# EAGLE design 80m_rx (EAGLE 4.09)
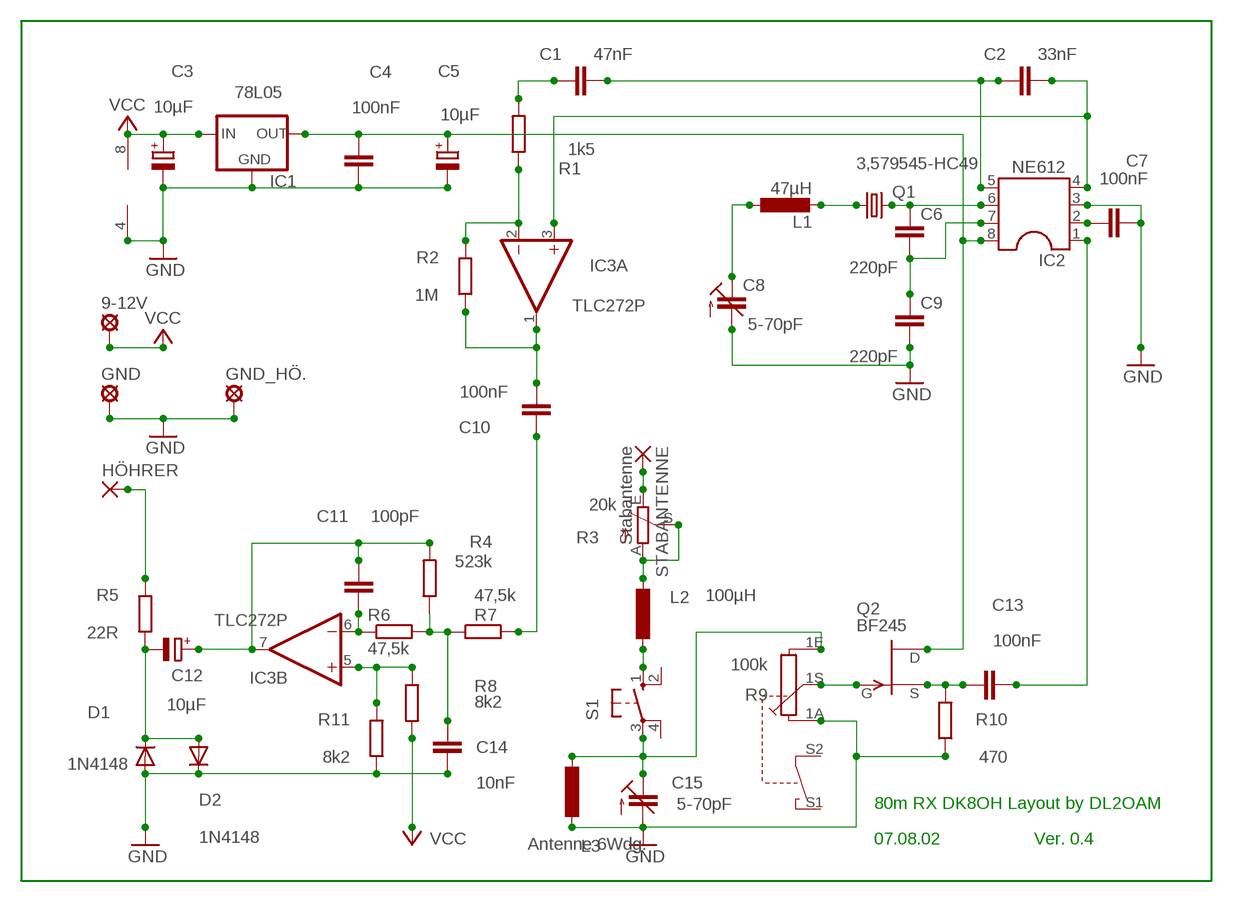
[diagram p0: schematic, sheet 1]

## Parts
9-12V  SE14  [SE14]
C1  47nF  C2.5/2  [C2.5-2]
C2  33nF  C-EU025-024X044  [C025-024X044]
C3  10µF  CPOL-EUE2.5-7  [E2,5-7]
C4  100nF  C-EU025_050-035X075  [C025_050-035X075]
C5  10µF  CPOL-EUE2.5-7  [E2,5-7]
C6  220pF  C2.5/2  [C2.5-2]
C7  100nF  C-EU025_050-025X075  [C025_050-025X075]
C8  5-70pF  C-TRIMM808-7.5  [CTRIM808-BC7.5]
C9  220pF  C2.5/2  [C2.5-2]
C10  100nF  C-EU025_050-025X075  [C025_050-025X075]
C11  100pF  C2.5/2  [C2.5-2]
C12  10µF  CPOL-EUE2.5-7  [E2,5-7]
C13  100nF  C-EU025_050-035X075  [C025_050-035X075]
C14  10nF  C-EU025-024X044  [C025-024X044]
C15  5-70pF  C-TRIMM808-7.5  [CTRIM808-BC7.5]
D1  1N4148  [DO35-10]
D2  1N4148  [DO35-10]
GND  SE14  [SE14]
GND_HÖ.  SE14  [SE14]
HÖHRER  3,81/1,1  [3,81/1,1]
IC1  78L05  78LXX  [78LXX]
IC2  NE612  DIL8  [DIL08]
IC3  TLC272P  [DIL08]
L1  47µH  L-EU0207/10  [0207/10]
L2  100µH  L-EU0207/12  [0207/12]
L3  Antenne 6Wdg.  L-EU0207/12  [0207/12]
Q1  3,579545-HC49  CRYTALHC49S  [HC49/S]
Q2  BF245  [TO92]
R1  1k5  R-EU_0207/10  [0207/10]
R2  1M  R-EU_0207/10  [0207/10]
R3  20k  TRIM_EU-S75H  [S75H]
R4  523k  R-EU_0207/10  [0207/10]
R5  22R  R-EU_0309/10  [0309/10]
R6  47,5k  R-EU_0309/10  [0309/10]
R7  47,5k  R-EU_0207/10  [0207/10]
R8  8k2  R-EU_0309/10  [0309/10]
R9  100k  PC16SV  [PC16SV]
R10  470  R-EU_0207/10  [0207/10]
R11  8k2  R-EU_0309/10  [0309/10]
S1  40-XX  [B3F-40XX]
STABANTENNE  Stabantenne  3,81/1,1  [3,81/1,1]

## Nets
8V: C4.1 C5.+ IC1.OUT IC2.8 Q2.1(D)
GND: C3.- C4.2 C5.- C7.2 C8.2(A) C9.2 C14.2 C15.2(A) D1.A D2.C GND.MP GND_HÖ..MP IC1.GND IC2.3 IC3.4(P:V-) L3.1 R9.1A R10.1 R11.1
N$2: R3.E STABANTENNE.1(P)
N$3: L2.2 R3.A R3.S
N$4: L2.1 S1.1(S)
N$5: C15.1(E) L3.2 R9.1E S1.3(P)
N$6: Q2.3(G) R9.1S
N$7: C13.1 Q2.2(S) R10.2
N$8: C7.1 IC2.2
N$11: C1.2 C2.1 IC2.5
N$12: C1.1 R1.2
N$15: IC3.2(A:-IN) R1.1 R2.2
N$16: C14.1 R4.1 R6.2 R7.1
N$17: C8.1(E) L1.1
N$18: C10.2 IC3.1(A:OUT) R2.1
N$19: C10.1 R7.2
N$20: C11.2 C12.+ IC3.7(B:OUT) R4.2
N$21: C12.- D1.C D2.A R5.1
N$22: HÖHRER.1(P) R5.2
N$24: C13.2 IC2.1
N$26: IC3.5(B:+IN) R8.1 R11.2
N$29: C11.1 IC3.6(B:-IN) R6.1
OSC: C6.1 IC2.6 Q1.2
OSC2: C6.2 C9.1 IC2.7
OSC3: L1.2 Q1.1
OUTPUTA: C2.2 IC2.4 IC3.3(A:+IN)
VCC: 9-12V.MP C3.+ IC1.IN IC3.8(P:V+) R8.2
Unconnected: R9.S1 R9.S2 S1.2(S1) S1.4(P1)

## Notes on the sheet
- 80m RX DK8OH Layout by DL2OAM
- 07.08.02 | Ver. 0.4

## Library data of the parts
9-12V GND GND_HÖ. = solpad:SE14: SOLDER PAD
C1 C6 C9 C11 = capacitor-wima:C: CAPACITOR
C2 C4 C7 C10 C13 C14 = rcl:C-EU: CAPACITOR, European symbol
C3 C5 C12 = rcl:CPOL-EU: POLARIZED CAPACITOR, European symbol
C8 C15 = rcl:C-TRIMM: Trimm capacitor
D1 D2 = diode:1N4148: DIODE
HÖHRER STABANTENNE = wirepad:3,81/1,1: THROUGH-HOLE PAD
IC1 = v-reg:78LXX: VOLTAGE REGULATOR
IC2 = dil:DIL8: SOCKET Dual In Line
IC3 = linear:TLC272: OP AMP
L1-L3 = rcl:L-EU: INDUCTOR, European symbol
Q1 = crystal:CRYTAL: CRYSTAL
Q2 = transistor-fet:BF245: N-Channel Junction FET
R1 R2 R4-R8 R10 R11 = rcl:R-EU_: RESISTOR, European symbol
R3 = pot:TRIM_EU-: POTENTIOMETER
R9 = piher:PC16SV: POTENTIOMETER vertical single carbon potentiometer with switch, 16 mm
S1 = switch-omron:40-XX: OMRON SWITCH

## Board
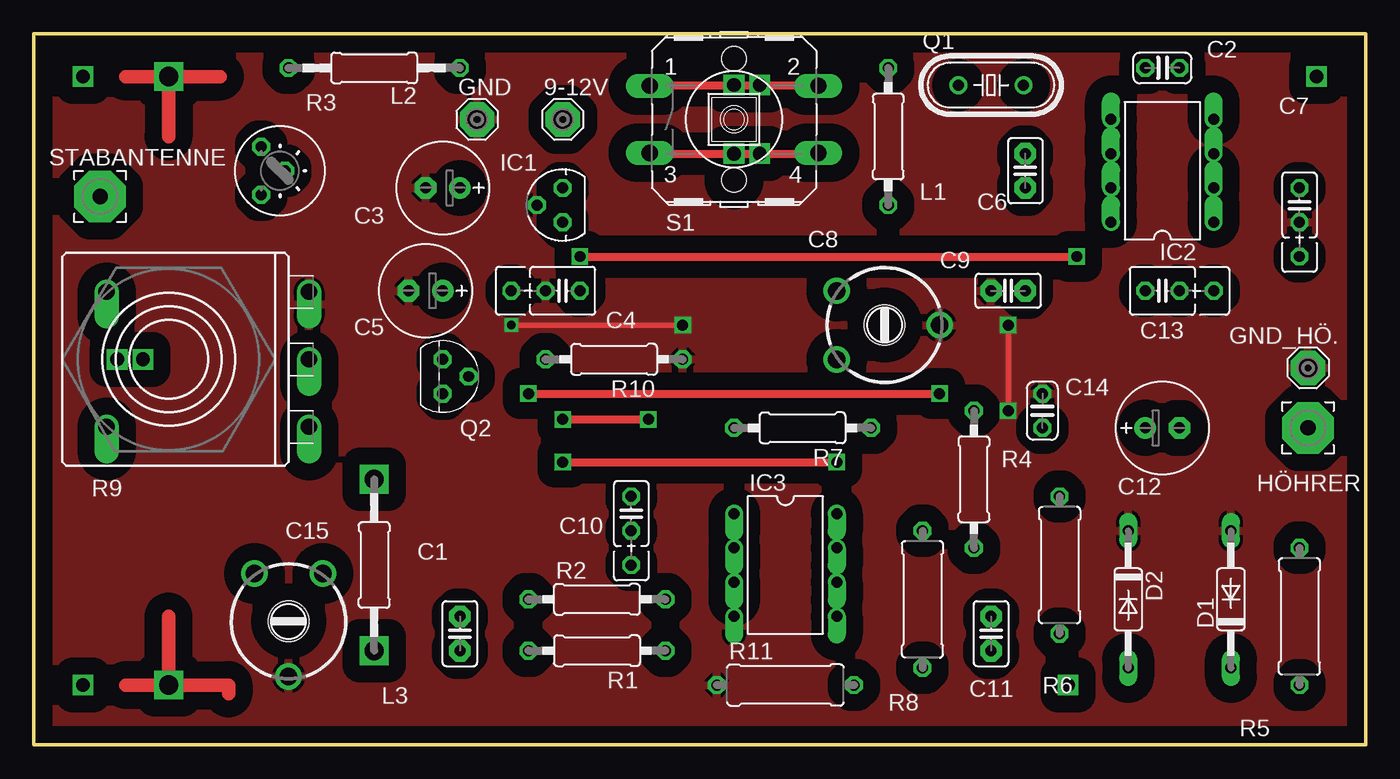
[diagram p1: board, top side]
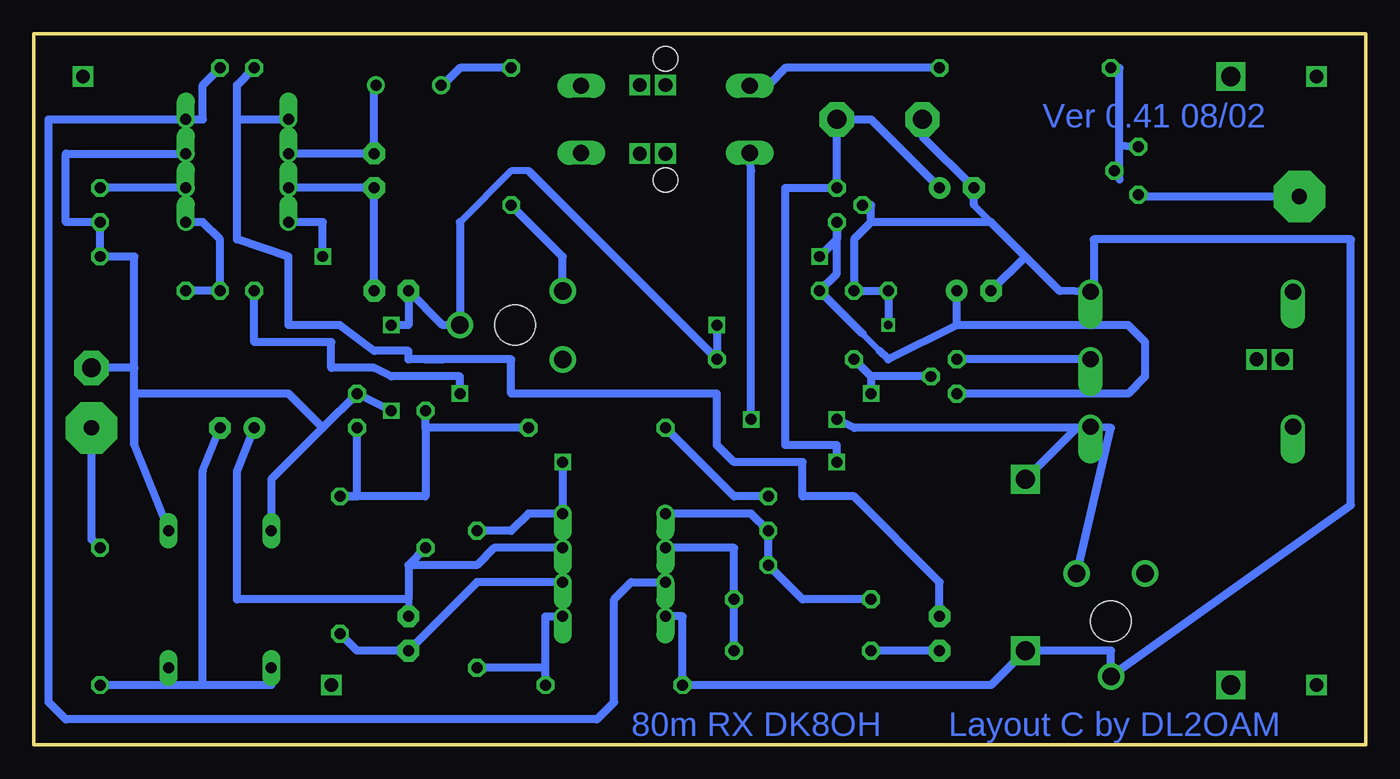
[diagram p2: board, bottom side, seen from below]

Size 98.73 x 52.7 mm. Coordinates in mm from the lower left corner, seen from the top.
Outline: 0,0 98.73,0 98.73,52.7 0,52.7 0,0
Copper layers used: Top, Bottom

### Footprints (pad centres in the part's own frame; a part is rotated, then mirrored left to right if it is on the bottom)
SE14 = drill 1.397 pad 2.54 octagon: MP 0,0
C2.5-2 = drill 0.813 pad 1.6 octagon: 1 -1.27,0; 2 1.27,0
C025-024X044 = drill 0.813 octagon: 1 -1.27,0; 2 1.27,0
E2,5-7 = drill 0.813 pad 1.6 round: + -1.27,0 | drill 0.813 pad 1.6 octagon: - 1.27,0
C025_050-035X075 = drill 0.813 octagon: 1 -1.27,0; 2 1.27,0; 3 3.81,0
C025_050-025X075 = drill 0.813 octagon: 1 -1.27,0; 2 1.27,0; 3 3.81,0
CTRIM808-BC7.5 = drill 1.3 round: 1 -2.54,-2.54; 2 0,5.08; 3 2.54,-2.54 | hole 3: 0,1
DO35-10 = drill 0.813 long: A 5.08,0; C -5.08,0
3,81/1,1 = drill 1.118 pad 3.81 octagon: 1 0,0
78LXX = drill 0.813 octagon: GND 0,1.905; IN 1.27,0; OUT -1.27,0
DIL08 = drill 0.813 offset: 1 -3.81,-3.81; 2 -1.27,-3.81; 3 1.27,-3.81; 4 3.81,-3.81; 5 3.81,3.81; 6 1.27,3.81; 7 -1.27,3.81; 8 -3.81,3.81
0207/10 = drill 0.813 octagon: 1 -5.08,0; 2 5.08,0
0207/12 = drill 0.813 octagon: 1 -6.35,0; 2 6.35,0
HC49/S = drill 0.813 round: 1 -2.413,0; 2 2.413,0
TO92 = drill 0.813 octagon: 1 1.27,0; 2 0,1.905; 3 -1.27,0
S75H = drill 0.813 octagon: A -1.778,-1.397; E 1.778,-1.397; S 0,0.381
0309/10 = drill 0.813 octagon: 1 -5.08,0; 2 5.08,0
PC16SV = drill 1.2 offset: 1A -5,10.4; 1E 5,10.4; 1S 0,10.4; S1 -5,-4.6; S2 5,-4.6
B3F-40XX = drill 1.194 long: 1 -6.248,2.489; 2 6.248,2.489; 3 -6.248,-2.489; 4 6.248,-2.489 | hole 1.803: 0,-4.496; 0,4.496

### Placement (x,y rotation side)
9-12V  39.2,46.35 0 top
C1  31.59,8.25 90 top
C2  83.66,50.16 0 top
C3  30.32,41.27 180 top
C4  39.2,33.65 180 top
C5  29.05,33.65 180 top
C6  73.5,42.54 270 top
C7  93.81,40 270 top
C8  62.06,31.11 270 top
C9  72.23,33.65 180 top
C10  44.28,17.14 270 top
C11  70.95,8.25 90 top
C12  83.66,23.49 0 top
C13  83.66,33.65 0 top
C14  74.77,24.76 90 top
C15  18.89,10.16 180 top
D1  88.73,10.79 90 top
D2  81.12,10.79 270 top
GND  32.85,46.35 0 top
GND_HÖ.  94.45,27.93 0 top
HÖHRER  94.45,23.49 0 top
IC1  39.2,40 90 top
IC2  83.66,42.54 90 top
IC3  55.71,13.33 270 top
L1  63.33,45.08 90 top
L2  25.23,50.16 180 top
L3  25.23,13.33 90 top
Q1  70.95,48.89 0 top
Q2  30.32,27.3 270 top
R1  41.74,6.98 180 top
R2  41.74,10.79 0 top
R3  18.25,42.54 270 top
R4  69.69,19.68 270 top
R5  93.81,9.52 90 top
R6  76.04,13.33 90 top
R7  56.98,23.49 180 top
R8  65.88,10.79 90 top
R9  10,28.57 270 top
R10  43.01,28.57 180 top
R11  55.71,4.44 0 top
S1  51.9,46.35 0 top
STABANTENNE  4.92,40.63 0 top

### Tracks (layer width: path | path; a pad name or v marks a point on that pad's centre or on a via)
8V  (via drill 0.81)
  Top 0.61: v40.47,36.19 v77.31,36.19
  Bottom 0.406: 36.03,29.2 37.3,30.47
  Bottom 0.61: v40.47,36.19 39.2,37.46 IC1.OUT 39.2,34.92 C4.1 37.3,30.47 | v77.31,36.19 77.31,38.73 IC2.8 | 30.32,31.11 35.39,28.57 36.03,29.2 | 30.32,31.11 C5.+ | 30.32,31.11 17.62,31.11 16.34,29.84 16.34,27.3 17.62,26.03 Q2.1
GND  (via drill 0.61, 0.81)
  Top 0.406: v72.23,31.11 v72.23,24.76 | v35.39,31.11 v48.09,31.11
  Bottom 0.508: 36.66,40 IC1.GND | 27.78,38.73 29.05,40 | 67.15,38.73 63.33,42.54 62.06,42.54
  Bottom 0.61: 77.31,23.49 C14.2 v72.23,24.76 | D2.C 81.12,19.68 77.31,23.49 | 91.28,22.22 D1.A | 91.28,22.22 91.28,27.93 GND_HÖ..MP | 91.28,26.03 91.28,22.22 | 77.31,23.49 79.84,26.03 91.28,26.03 | 36.66,38.73 37.93,37.46 C4.2 35.39,33.65 v35.39,31.11 | 36.66,38.73 36.66,40 | GND.MP 32.85,45.08 C3.- 29.05,40 | 25.23,36.19 22.7,33.65 R9.1A | 25.23,36.19 27.78,38.73 36.66,38.73 | IC3.4 50.63,9.52 R11.1 27.78,4.44 L3.1 18.89,6.98 C15.2 | C15.2 18.89,4.44 | IC2.3 96.36,43.81 96.36,38.73 C7.2 93.81,36.19 91.28,36.19 91.28,26.03 | 25.23,36.19 C5.- | 62.06,42.54 R10.1 v48.09,31.11 | 67.15,38.73 C8.2 68.42,31.11 C9.2 70.95,31.11 v72.23,31.11 | C15.2 1.1,17.77 1.1,37.46 20.16,37.46 20.16,33.65 20.79,33.65
  pour Top (isolate 1.27, rank 3): 0.47,52.06 0.47,-0.01 98.9,-0.01 98.9,52.7 0.47,52.7
N$2
  Bottom 0.61: R3.E 16.98,40.76 16.98,40.63 STABANTENNE.1
N$3
  Bottom 0.508: 18.89,42.54 R3.S 18.25,42.54
  Bottom 0.61: L2.2 18.25,50.16 18.25,44.45 | 18.25,41.91 18.25,42.54 18.25,44.45 | 18.25,44.45 R3.A
N$4
  Bottom 0.61: L2.1 43.01,50.16 44.28,48.89 S1.1
N$5  (via drill 0.81)
  Top 0.61: v39.2,24.12 v45.55,24.12
  Bottom 0.508: R9.1E 20.16,23.49
  Bottom 0.61: L3.2 21.43,23.49 R9.1E 18.89,23.49 C15.1 | v45.55,24.12 45.55,42.54 S1.3 | 20.16,23.49 37.93,23.49 v39.2,24.12
N$6
  Bottom 0.61: R9.1S Q2.3
N$7  (via drill 0.81)
  Top 0.61: v36.66,26.03 v67.15,26.03
  Bottom 0.61: 36.66,27.3 R10.2 | Q2.2 36.66,27.3 | C13.1 82.39,29.84 76.67,29.84 76.67,27.93 73.5,27.93 72.23,27.3 67.15,27.3 v67.15,26.03 | 36.66,27.3 v36.66,26.03
N$8
  Bottom 0.61: IC2.2 C7.1
N$9  (via drill 1.02)
  Top 0.61: 45.55,48.89 v51.9,48.89 v53.81,48.89 58.25,48.89
N$10  (via drill 1.02)
  other vias: 8.09,28.57
N$11
  Bottom 0.61: C1.2 31.59,12.06 37.93,18.41 41.74,18.41 41.74,20.95 46.82,20.95 48.09,22.22 48.09,26.03 63.33,26.03 63.33,28.57 69.69,28.57 | 69.69,28.57 68.42,28.57 | 69.69,28.57 70.95,28.57 70.95,29.2 73.5,29.2 76.04,31.11 79.84,31.11 79.84,36.19 83.66,37.46 83.66,46.35 | 83.66,46.35 83.66,48.89 C2.1 | 83.66,46.35 IC2.5
N$12
  Bottom 0.61: C1.1 R1.2
N$13  (via drill 1.02)
  other vias: 6.19,28.57
N$15
  Bottom 0.61: R1.1 R2.2 46.82,14.6 IC3.2
N$16
  Bottom 0.61: R7.1 69.69,23.49 | 69.69,23.49 R4.1 | C14.1 74.77,18.41 R6.2 69.69,18.41 69.69,23.49
N$17
  Bottom 0.61: L1.1 59.52,36.19 C8.1
N$18
  Bottom 0.61: R2.1 41.74,10.79 44.28,13.33 C10.2 45.55,17.14 IC3.1
N$19
  Bottom 0.61: C10.1 46.82,18.41 R7.2
N$20
  Bottom 0.508: 70.95,10.79 C11.2
  Bottom 0.61: 70.95,13.33 70.95,10.79 83.66,10.79 83.66,20.31 C12.+ | 70.95,13.33 R4.2 | 70.95,13.33 65.88,13.33 64.61,14.6 IC3.7
N$21
  Bottom 0.61: D2.A 81.12,4.44 86.2,4.44 | 86.2,4.44 R5.1 | 86.2,4.44 88.73,4.44 D1.C | 86.2,4.44 86.2,20.31 C12.-
N$22
  Bottom 0.61: HÖHRER.1 94.45,15.24 R5.2
N$23  (via drill 1.02)
  Top 0.61: 58.25,43.81 v53.81,43.81 v51.9,43.81 45.55,43.81
N$24
  Bottom 0.61: 87.47,33.65 C13.2 84.92,37.46 86.2,38.73 IC2.1
N$26
  Bottom 0.61: 60.79,5.71 60.79,9.52 IC3.5 | R11.2 60.79,5.71 | 60.79,5.71 R8.1
N$27  (via drill 1.02)
  other vias: 3.65,49.52
N$28  (via drill 1.02)
  other vias: 3.65,4.44
N$29
  Bottom 0.61: R6.1 74.77,6.98 C11.1 65.88,12.06 IC3.6
N$30  (via drill 1.02)
  other vias: 95.09,49.52
N$31  (via drill 1.02)
  other vias: 76.67,4.44
N$32  (via drill 1.42)
  other vias: 25.23,19.68
N$33  (via drill 1.42)
  other vias: 25.23,6.98
N$34  (via drill 1.42)
  Top 1.016: v10,4.44 14.44,4.44 14.44,3.8 | 9.36,4.44 v10,4.44 | v10,4.44 10,9.52 | v10,4.44 6.82,4.44
N$35  (via drill 1.42)
  Top 1.016: v10,49.52 10,45.08 | v10,49.52 13.8,49.52 | v10,49.52 6.82,49.52
OSC
  Bottom 0.61: Q1.2 73.5,48.89 C6.1 IC2.6
OSC2
  Bottom 0.61: IC2.7 C6.2 C9.1
OSC3
  Bottom 0.61: L1.2 67.15,50.16 68.42,48.89 Q1.1
OUTPUTA
  Bottom 0.508: 86.2,46.35 IC2.4
  Bottom 0.61: C2.2 86.2,48.89 86.2,46.35 97.62,46.35 97.62,3.17 96.36,1.9 56.98,1.9 55.71,3.17 55.71,10.79 54.45,12.06 IC3.3
VCC  (via drill 0.81, 0.81 pad 0.3)
  Top 0.61: v39.2,20.95 v59.52,20.95
  Bottom 0.61: R8.2 63.33,15.87 62.06,17.14 IC3.8 v59.52,20.95 | C3.+ 36.66,46.35 9-12V.MP IC1.IN 43.01,41.27 43.01,22.22 39.2,22.22 v39.2,20.95

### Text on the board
Bottom: Ver 0.41 08/02 | Layout C by DL2OAM | 80m RX DK8OH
